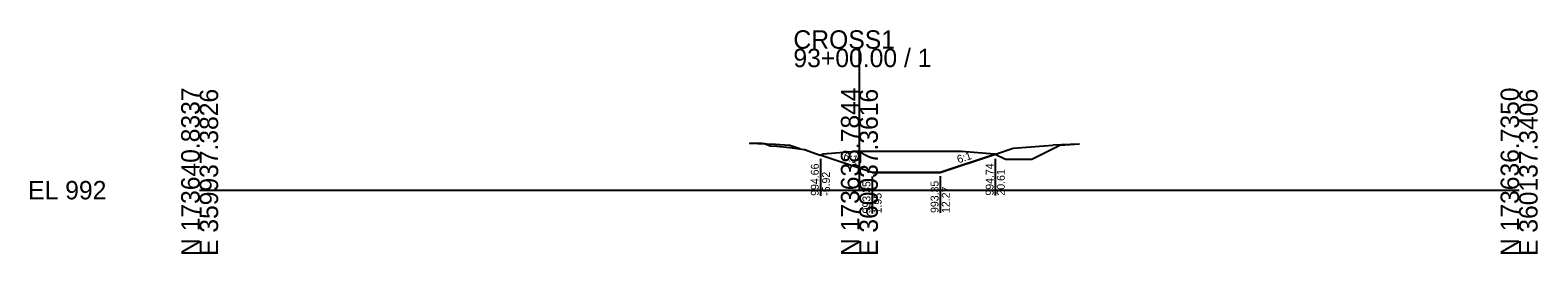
# Model space of a CAD drawing. Extents: x -26 to 1403, y -10 to 11027.
# Drawn here: x -25.7 to 202.8, y 7990.3 to 8024.3 of the extents above; entities that cross this region are included whole.
import ezdxf

# ---------------------------------------------------------------- set-up
doc = ezdxf.new("R2010")
doc.units = 0
for name, color, linetype in [('Default', 7, 'Continuous'), ('P_E_XS_Ground', 7, 'Continuous'), ('P_XS', 7, 'Continuous'), ('P_XS_EAR_CommonGrnd', 7, 'Continuous'), ('P_XS_Lane', 7, 'Continuous'), ('P_XS_Rock', 7, 'Continuous')]:
    doc.layers.add(name, color=color, linetype=linetype)

msp = doc.modelspace()

# ---------------------------------------------------------------- linework, layer by layer
at = {"layer": 'Default'}
for p, q in [((100, 8000), (100, 8021.5)), ((0, 8000), (100, 8000)), ((100, 8000), (200, 8000))]:
    msp.add_line(p, q, dxfattribs=at)
at = {"layer": 'P_E_XS_Ground'}
for p, q in [((83.42, 8007.17), (83.97, 8007.13)), ((83.97, 8007.13), (85.23, 8007.14)), ((85.23, 8007.14), (85.6, 8007.1)), ((85.6, 8007.1), (86.46, 8006.72)), ((86.46, 8006.72), (87.48, 8006.68)), ((87.48, 8006.68), (89.44, 8006.5)), ((89.44, 8006.5), (90.17, 8006.4)), ((90.17, 8006.4), (91.7, 8006.19)), ((91.7, 8006.19), (94.08, 8005.32)), ((94.08, 8005.32), (94.5, 8005.53)), ((94.5, 8005.53), (99.5, 8005.93)), ((99.5, 8005.93), (115.5, 8005.93)), ((115.5, 8005.93), (120.5, 8005.53)), ((120.5, 8005.53), (122.16, 8004.7)), ((126.16, 8004.7), (130.4, 8006.82)), ((130.4, 8006.82), (130.42, 8006.83)), ((130.42, 8006.83), (132.63, 8006.97)), ((132.63, 8006.97), (133.37, 8007.02)), ((122.16, 8004.7), (126.16, 8004.7))]:
    msp.add_line(p, q, dxfattribs=at)
at = {"layer": 'P_XS'}
for p, q in [((83.3, 8007.17), (87.3, 8007.01)), ((87.3, 8007.01), (89.3, 8006.85)), ((90.97, 8006.29), (89.3, 8006.85)), ((120.61, 8005.47), (123.3, 8006.37)), ((123.3, 8006.37), (129.3, 8006.85)), ((133.3, 8007.01), (129.3, 8006.85))]:
    msp.add_line(p, q, dxfattribs=at)
at = {"layer": 'P_XS_EAR_CommonGrnd'}
msp.add_lwpolyline([(120.5, 8005.53), (120.61, 8005.47), (112.27, 8002.7), (101.95, 8002.7), (94.08, 8005.32), (94.5, 8005.53), (99.5, 8005.93), (115.5, 8005.93)], close=True, dxfattribs=at)
at = {"layer": 'P_XS_Lane'}
for p, q in [((101.95, 8002.7), (94.08, 8005.32)), ((112.27, 8002.7), (120.61, 8005.47)), ((101.95, 8002.7), (112.27, 8002.7))]:
    msp.add_line(p, q, dxfattribs=at)
at = {"layer": 'P_XS_Rock'}
for p, q in [((94.09, 8004.75), (94.09, 7999.14)), ((120.59, 8004.78), (120.59, 7999.17)), ((101.92, 8002.07), (101.92, 7996.46)), ((112.25, 8002.14), (112.25, 7996.53))]:
    msp.add_line(p, q, dxfattribs=at)

# ---------------------------------------------------------------- texts
at = {"layer": 'Default'}
for s, p in [('CROSS1', (90, 8021.5)), ('93+00.00 / 1', (90, 8018.7)), ('EL 992', (-26, 7998.6))]:
    msp.add_text(s, height=2.8, dxfattribs=at).set_placement(p)
for s, p in [('N 173640.8337', (0, 7990)), ('E 359937.3826', (2.8, 7990)), ('N 173638.7844', (100, 7990)), ('E 360037.3616', (102.8, 7990)), ('N 173636.7350', (200, 7990)), ('E 360137.3406', (202.8, 7990))]:
    msp.add_text(s, height=2.8, rotation=90, dxfattribs=at).set_placement(p)
at = {"layer": 'P_XS_Rock'}
for s, rotation, p in [('6:1', 341.5651, (97.46, 8004.7)), ('6:1', 18.4349, (115.02, 8004.06)), ('994.66', 90, (93.84, 7999.14)), ('994.74', 90, (120.34, 7999.17)), ('-5.92', 90, (95.54, 7999.14)), ('993.35', 90, (101.67, 7996.46)), ('993.35', 90, (112, 7996.53)), ('20.61', 90, (122.04, 7999.17)), ('1.95', 90, (103.37, 7996.46)), ('12.27', 90, (113.7, 7996.53))]:
    msp.add_text(s, height=1.2, rotation=rotation, dxfattribs=at).set_placement(p)

doc.saveas('drawing.dxf')
